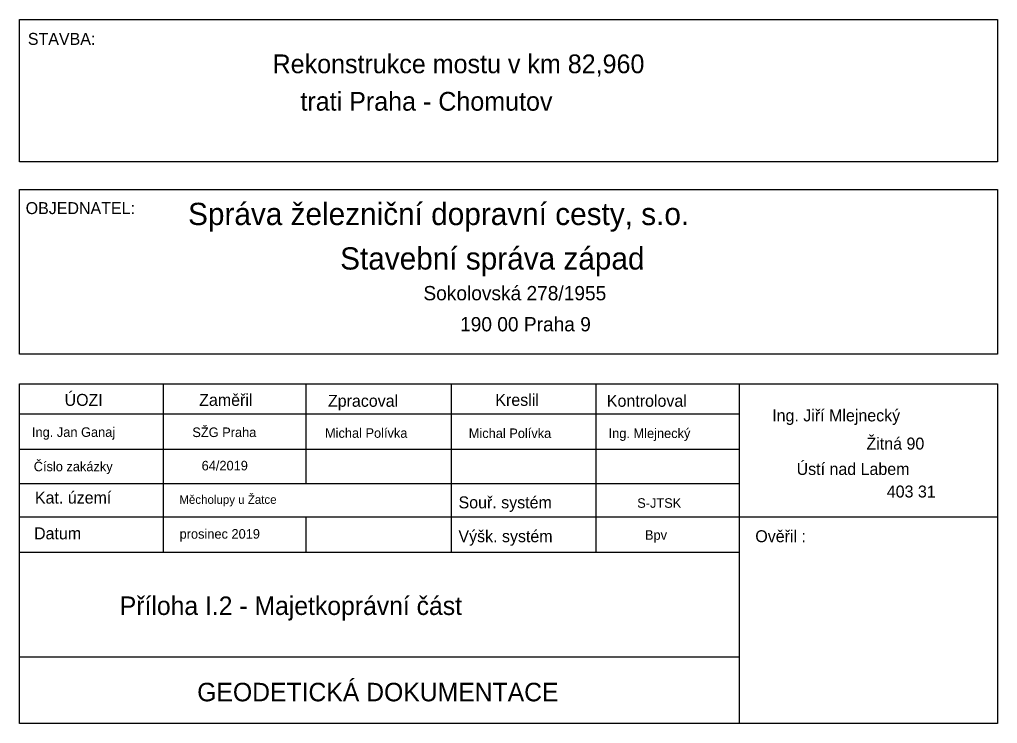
# Model space of a CAD drawing. Extents: x -879530 to -879371, y -1019242 to -1019127.
import ezdxf

# ---------------------------------------------------------------- set-up
doc = ezdxf.new("R2010")
doc.units = 0
doc.layers.add('LEGENDA', color=7, linetype='Continuous')
doc.layers.add('tabulka', color=7, linetype='Continuous')

msp = doc.modelspace()

# ---------------------------------------------------------------- linework, layer by layer
at = {"layer": 'tabulka'}
for p, q in [((-879530.09, -1019186.45), (-879371.44, -1019186.45)), ((-879506.8, -1019186.45), (-879506.8, -1019213.77)), ((-879483.66, -1019186.45), (-879483.66, -1019202.65)), ((-879460.06, -1019186.45), (-879460.06, -1019213.77)), ((-879436.61, -1019186.45), (-879436.61, -1019213.77)), ((-879413.31, -1019241.58), (-879413.31, -1019186.45)), ((-879530.09, -1019191.36), (-879413.31, -1019191.36)), ((-879530.09, -1019197.07), (-879413.31, -1019197.07)), ((-879530.09, -1019202.65), (-879413.31, -1019202.65)), ((-879530.09, -1019208.07), (-879371.44, -1019208.07)), ((-879483.66, -1019208.07), (-879483.66, -1019213.77)), ((-879530.09, -1019213.77), (-879413.31, -1019213.77)), ((-879530.09, -1019230.76), (-879413.31, -1019230.76))]:
    msp.add_line(p, q, dxfattribs=at)
for points in [[(-879530.09, -1019127.36), (-879371.44, -1019127.36), (-879371.44, -1019150.43), (-879530.09, -1019150.43)], [(-879530.09, -1019154.95), (-879371.44, -1019154.95), (-879371.44, -1019181.64), (-879530.09, -1019181.64)]]:
    msp.add_lwpolyline(points, close=True, dxfattribs=at)
msp.add_lwpolyline([(-879371.44, -1019186.45), (-879371.44, -1019241.58), (-879530.09, -1019241.58), (-879530.09, -1019186.45)], dxfattribs=at)

# ---------------------------------------------------------------- texts
at = {"layer": 'LEGENDA'}
for s, p in [('Rekonstrukce mostu v km 82,960 ', (-879489.04, -1019136.07)), ('    trati Praha - Chomutov', (-879489.04, -1019142.15))]:
    msp.add_text(s, height=3.04, dxfattribs=at).set_placement(p)
at = {"layer": 'tabulka'}
for s, height, p in [('STAVBA:', 1.94, (-879528.75, -1019131.47)), ('OBJEDNATEL:', 1.94, (-879529.1, -1019158.93)), ('Správa železniční dopravní cesty, s.o.', 3.61, (-879502.75, -1019160.71)), ('Stavební správa západ', 3.61, (-879478.08, -1019167.93)), ('Sokolovská 278/1955', 2.32, (-879464.57, -1019172.92)), ('190 00 Praha 9', 2.32, (-879458.62, -1019177.96)), ('ÚOZI', 1.94, (-879522.79, -1019190.05)), ('Zaměřil', 1.94, (-879500.95, -1019190.05)), ('Zpracoval', 1.94, (-879480.06, -1019190.2)), ('Kreslil', 1.94, (-879452.9, -1019190.05)), ('Kontroloval', 1.94, (-879434.81, -1019190.2)), ('Ing. Jiří Mlejnecký', 1.94, (-879407.98, -1019192.57)), ('Ing. Jan Ganaj', 1.552, (-879528.08, -1019195.08)), ('SŽG Praha', 1.552, (-879502.06, -1019195.11)), ('Michal Polívka', 1.552, (-879480.54, -1019195.23)), ('Michal Polívka', 1.552, (-879457.21, -1019195.27)), ('Ing. Mlejnecký', 1.552, (-879434.52, -1019195.27)), ('Žitná 90', 1.94, (-879392.68, -1019197.14)), ('Číslo zakázky', 1.552, (-879527.79, -1019200.66)), ('64/2019', 1.552, (-879500.55, -1019200.52)), ('Ústí nad Labem', 1.94, (-879404.02, -1019201.26)), ('403 31', 1.94, (-879389.39, -1019204.92)), ('Kat. území', 1.94, (-879527.6, -1019205.91)), ('Měcholupy u Žatce', 1.3968, (-879504.17, -1019205.95)), ('Souř. systém', 1.94, (-879458.87, -1019206.68)), ('S-JTSK', 1.552, (-879429.88, -1019206.59)), ('Datum', 1.94, (-879527.74, -1019211.71)), ('prosinec 2019', 1.552, (-879504.13, -1019211.6)), ('Výšk. systém', 1.94, (-879458.89, -1019212.17)), ('Bpv', 1.552, (-879428.62, -1019211.78)), ('Ověřil :', 1.94, (-879410.72, -1019212.17)), ('Příloha I.2 - Majetkoprávní část', 3, (-879513.83, -1019223.98)), ('GEODETICKÁ DOKUMENTACE ', 3, (-879501.27, -1019237.99))]:
    msp.add_text(s, height=height, dxfattribs=at).set_placement(p)

doc.saveas('drawing.dxf')
